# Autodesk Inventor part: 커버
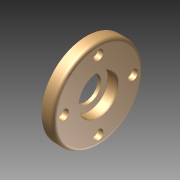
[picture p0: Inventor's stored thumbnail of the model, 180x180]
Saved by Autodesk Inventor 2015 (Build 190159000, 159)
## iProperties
Created: 2024-12
Part Number: 커버
Material: 일반
Document SubType Name: Modeling
Designer: 102566
Density: 1 g/cm^3
Appearance: 기본값
Author: 102566
Author: jhkim
Creation Date: 2024-11-28
Sending System: Autodesk Inventor 2025
Preprocessor: ST-DEVELOPER v20
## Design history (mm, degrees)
node "커버1"
node "솔리드1"
node "기준1"
